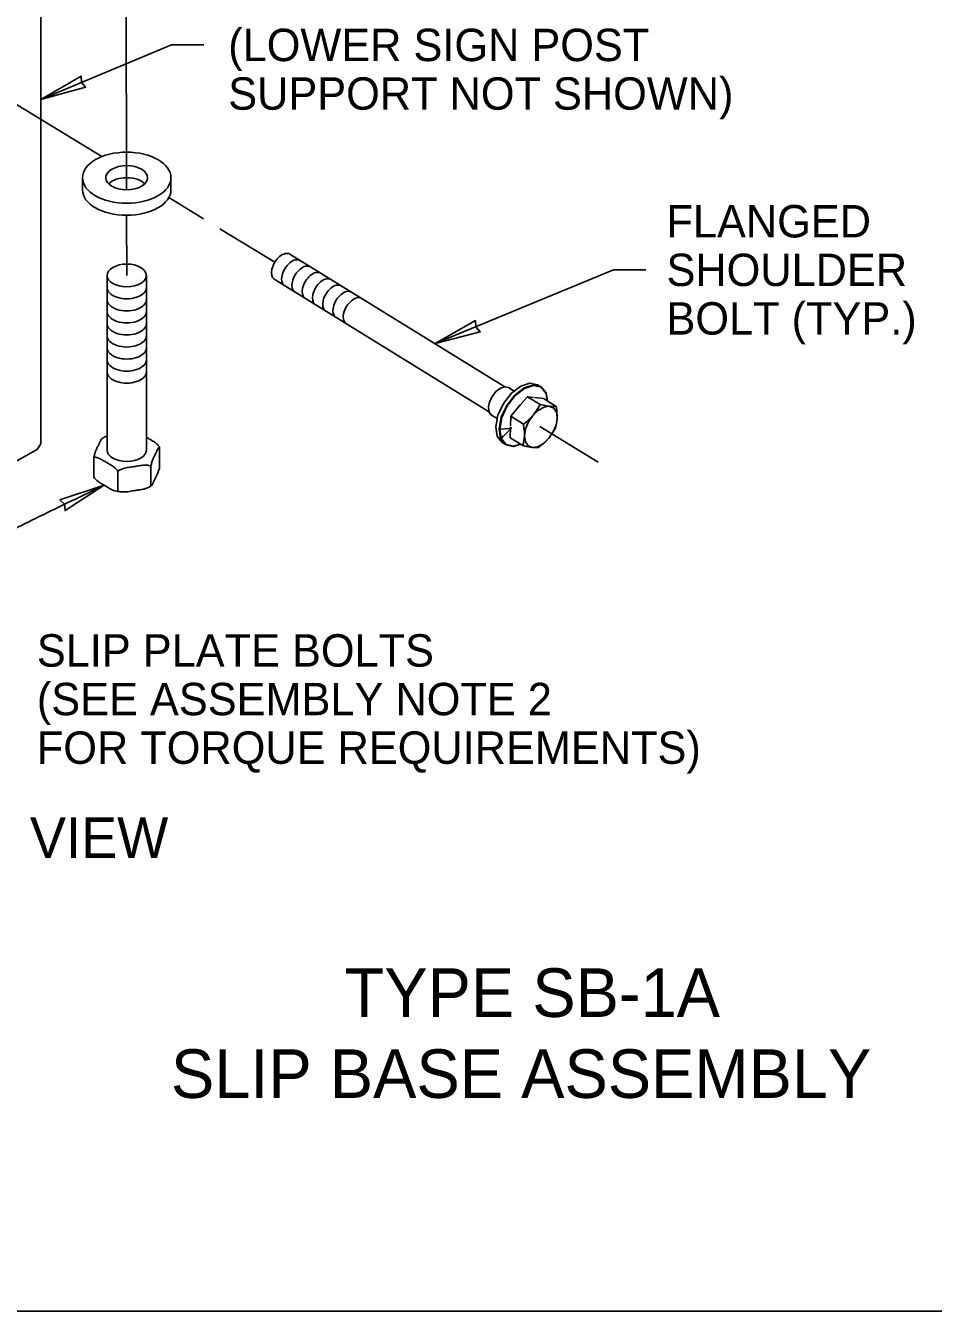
# Model space of a CAD drawing. Extents: x 99862 to 103151, y 99997 to 117076.
# Drawn here: x 100348 to 100796, y 112000 to 112634 of the extents above; entities that cross this region are included whole.
import ezdxf

# ---------------------------------------------------------------- set-up
doc = ezdxf.new("R2010")
doc.units = 0
for name, color, linetype in [('Level 1', 7, 'Continuous'), ('Level 12', 7, 'Continuous'), ('Level 13', 7, 'Continuous'), ('Level 15', 7, 'Continuous'), ('Level 20', 7, 'Continuous'), ('Level 3', 7, 'Continuous'), ('Level 4', 7, 'Continuous'), ('Level 5', 7, 'Continuous'), ('Level 9', 7, 'Continuous')]:
    doc.layers.add(name, color=color, linetype=linetype)

msp = doc.modelspace()

# ---------------------------------------------------------------- linework, layer by layer
at = {"layer": 'Level 1'}
msp.add_lwpolyline([(99862, 111999.5), (103151, 111999.5), (103151, 114075.5), (99862, 114075.5)], close=True, dxfattribs=at)
at = {"layer": 'Level 12'}
for p, q in [((100375.72, 112559.31), (100375.72, 112553.37)), ((100419.42, 112559.31), (100419.42, 112553.37)), ((100387.86, 112424.8), (100387.86, 112511.05)), ((100407.28, 112424.8), (100407.28, 112511.05)), ((100413.82, 112416.42), (100413.82, 112426.33)), ((100381.32, 112421.3), (100381.32, 112411.39)), ((100393.22, 112414.43), (100393.22, 112404.52)), ((100409.46, 112416.95), (100409.46, 112407.03))]:
    msp.add_line(p, q, dxfattribs=at)
for centre, major_axis in [((100397.57, 112559.31), (-21.85, 0)), ((100397.57, 112559.31), (-10.32, 0)), ((100397.57, 112511.05), (-9.71, 0))]:
    msp.add_ellipse(centre, major_axis=major_axis, ratio=0.57735, dxfattribs=at)
for centre, major_axis, start_param, end_param in [((100397.57, 112553.37), (-10.32, 0), 3.664192, 5.760586), ((100397.57, 112553.37), (21.85, 0), 3.141593, 6.283185), ((100397.57, 112505.1), (9.71, 0), 3.141588, 6.283185), ((100397.57, 112499.15), (9.71, 0), 3.141588, 6.283185), ((100397.57, 112493.2), (9.71, 0), 3.141588, 6.283185), ((100397.57, 112487.26), (9.71, 0), 3.141588, 6.283185), ((100397.57, 112481.31), (9.71, 0), 3.141588, 6.283185), ((100397.57, 112475.36), (9.71, 0), 3.141588, 6.283185), ((100397.57, 112469.41), (9.71, 0), 3.141588, 6.283185), ((100397.57, 112463.47), (9.71, 0), 3.141588, 6.283185), ((100397.57, 112424.8), (9.71, 0), 3.141593, 6.283185)]:
    msp.add_ellipse(centre, major_axis=major_axis, ratio=0.57735, start_param=start_param, end_param=end_param, dxfattribs=at)
for points, degree in [([(100387.86, 112431.72), (100387.5, 112431.6), (100387.15, 112431.47), (100386.64, 112431.24), (100386.46, 112431.15), (100386.28, 112431.05)], 3), ([(100385.55, 112430.63), (100385.49, 112430.6), (100385.43, 112430.54), (100384.81, 112429.88), (100384.09, 112428.26), (100383.5, 112426.98), (100382.9, 112425.69), (100382.19, 112424.24), (100381.53, 112422.09), (100381.42, 112421.7), (100381.32, 112421.3)], 3), ([(100386.28, 112431.05), (100386.06, 112430.93), (100385.84, 112430.81), (100385.61, 112430.67), (100385.58, 112430.65), (100385.55, 112430.63)], 3), ([(100413.82, 112426.33), (100413.56, 112426.67), (100413.25, 112427), (100411.44, 112428.77), (100409.5, 112429.81), (100407.87, 112430.75), (100407.68, 112430.86), (100407.48, 112430.97), (100407.28, 112431.09)], 3), ([(100413.82, 112426.33), (100413.72, 112426.32), (100413.61, 112426.23), (100412.95, 112425.53), (100412.24, 112423.9), (100411.64, 112422.62), (100411.05, 112421.34), (100410.33, 112419.89), (100409.67, 112417.74), (100409.56, 112417.34), (100409.46, 112416.95)], 3), ([(100393.22, 112414.43), (100392.96, 112414.78), (100392.65, 112415.11), (100390.84, 112416.87), (100388.89, 112417.91), (100387.27, 112418.85), (100385.64, 112419.79), (100383.69, 112421), (100381.88, 112421.32), (100381.58, 112421.35), (100381.32, 112421.3)], 3), ([(100409.46, 112416.95), (100409.11, 112417.09), (100408.69, 112417.18), (100406.22, 112417.52), (100403.56, 112417.02), (100401.34, 112416.68), (100399.12, 112416.33), (100396.46, 112416), (100393.99, 112414.9), (100393.57, 112414.68), (100393.22, 112414.43)], 3), ([(100409.59, 112407.08), (100409.65, 112407.12), (100409.71, 112407.17), (100410.33, 112407.84), (100411.05, 112409.46), (100411.64, 112410.74), (100412.24, 112412.02), (100412.95, 112413.47), (100413.61, 112415.62), (100413.72, 112416.02), (100413.82, 112416.42)], 3), ([(100381.32, 112411.39), (100381.58, 112411.04), (100381.88, 112410.71), (100383.69, 112408.95), (100385.64, 112407.91), (100387.27, 112406.97), (100388.87, 112406.04), (100390.78, 112404.86), (100392.31, 112404.56)], 3), ([(100394.56, 112404.21), (100396.62, 112403.98), (100399.19, 112404.46), (100401.34, 112404.79), (100403.56, 112405.13), (100406.22, 112405.46), (100408.5, 112406.48), (100408.68, 112406.57), (100408.87, 112406.67)], 3), ([(100408.86, 112406.66), (100409.08, 112406.78), (100409.3, 112406.9), (100409.53, 112407.04), (100409.56, 112407.06), (100409.59, 112407.08)], 3), ([(100392.31, 112404.56), (100393.06, 112404.41), (100393.81, 112404.3), (100394.56, 112404.21)], 2)]:
    msp.add_open_spline(points, degree=degree, dxfattribs=at)
at = {"layer": 'Level 13'}
for p, q in [((100584.37, 112456.08), (100478.11, 112521.57)), ((100576.32, 112443.93), (100470.47, 112509.17))]:
    msp.add_line(p, q, dxfattribs=at)
for centre, start_param, end_param in [((100474.29, 112515.37), 6.283173, 9.424785), ((100479.35, 112512.25), 6.283174, 9.424783), ((100484.42, 112509.13), 6.283172, 9.424785), ((100489.48, 112506.01), 6.283179, 9.424784), ((100494.55, 112502.88), 6.283177, 9.424782), ((100499.62, 112499.76), 6.283174, 9.424785), ((100504.68, 112496.64), 6.283176, 9.424783), ((100509.75, 112493.52), 6.283178, 9.42478)]:
    msp.add_ellipse(centre, major_axis=(3.82, 6.2), ratio=0.57735, start_param=start_param, end_param=end_param, dxfattribs=at)
at = {"layer": 'Level 15'}
for p, q in [((100397.47, 112553.36), (100397.16, 112677.54)), ((100355.06, 112597.97), (100419.74, 112624.88)), ((100435.74, 112624.88), (100419.74, 112624.88)), ((100385.2, 112569.71), (100315.22, 112612.39)), ((100435.56, 112539.01), (100418.37, 112549.49)), ((100397.57, 112511.05), (100397.5, 112540.75)), ((100470.71, 112517.58), (100443.53, 112534.15)), ((100549.96, 112477.36), (100638.07, 112513.82)), ((100654.07, 112513.82), (100638.07, 112513.82)), ((100630.48, 112418.83), (100601.66, 112436.41))]:
    msp.add_line(p, q, dxfattribs=at)
for points in [[(100355.06, 112597.97), (100377.28, 112603.99), (100375.16, 112606.34), (100374.99, 112609.5)], [(100549.96, 112477.36), (100572.21, 112483.25), (100570.11, 112485.61), (100569.95, 112488.77)], [(100386.47, 112407.43), (100367.14, 112394.91), (100366.81, 112398.06), (100364.57, 112400.3)]]:
    msp.add_lwpolyline(points, close=True, dxfattribs=at)
msp.add_open_spline([(100325.17, 112301.86), (100160.65, 112301.86), (100386.47, 112407.43)], degree=2, dxfattribs=at)
at = {"layer": 'Level 3'}
for p, q in [((100598.56, 112456.57), (100598.58, 112456.63)), ((100589.56, 112451.64), (100589.54, 112451.68)), ((100594.09, 112455.13), (100594.09, 112455.18)), ((100602.3, 112455.74), (100602.34, 112455.8)), ((100604.78, 112452.82), (100602.34, 112455.8)), ((100604.82, 112453.08), (100605.48, 112448.99)), ((100585.65, 112446.63), (100585.62, 112446.65)), ((100602.22, 112447.22), (100602.11, 112447.18)), ((100582.98, 112440.87), (100582.94, 112440.87)), ((100581.57, 112435.19), (100582.34, 112430.44)), ((100581.94, 112435.23), (100581.89, 112435.21)), ((100587.13, 112435.09), (100582.65, 112430.53)), ((100582.63, 112430.66), (100582.34, 112430.44)), ((100584.82, 112427.41), (100582.34, 112430.44)), ((100585.12, 112427.61), (100585.09, 112427.55)), ((100588.86, 112426.78), (100588.84, 112426.72))]:
    msp.add_line(p, q, dxfattribs=at)
for points in [[(100593.96, 112455.48), (100598.53, 112456.95), (100598.53, 112456.95)], [(100598.57, 112456.57), (100598.58, 112456.63), (100594.09, 112455.18)], [(100598.53, 112456.95), (100602.34, 112456.11), (100602.34, 112456.11)], [(100602.31, 112455.74), (100602.34, 112455.8), (100598.58, 112456.63)], [(100585.36, 112446.81), (100589.34, 112451.92), (100589.34, 112451.92)], [(100589.56, 112451.65), (100589.54, 112451.68), (100585.62, 112446.65)], [(100589.34, 112451.92), (100593.96, 112455.48), (100593.96, 112455.48)], [(100594.1, 112455.13), (100594.09, 112455.18), (100589.54, 112451.68)], [(100602.34, 112456.11), (100604.82, 112453.08), (100604.82, 112453.08)], [(100604.73, 112452.77), (100604.78, 112452.82), (100605.39, 112449.05)], [(100582.63, 112440.94), (100585.36, 112446.81), (100585.36, 112446.81)], [(100585.66, 112446.64), (100585.62, 112446.65), (100582.94, 112440.87)], [(100581.57, 112435.19), (100581.57, 112435.19), (100582.63, 112440.94), (100582.63, 112440.94)], [(100582.99, 112440.88), (100582.94, 112440.87), (100581.89, 112435.21)], [(100581.57, 112435.19), (100586.91, 112435.42), (100587.84, 112435.81)], [(100581.61, 112435.19), (100581.6, 112435.19), (100581.6, 112435.19), (100581.57, 112435.19)], [(100581.94, 112435.25), (100581.89, 112435.21), (100582.65, 112430.53)], [(100583.67, 112431.85), (100582.65, 112430.53), (100585.09, 112427.55)], [(100588.63, 112426.57), (100584.82, 112427.41), (100584.82, 112427.41)], [(100585.12, 112427.61), (100585.09, 112427.55), (100588.84, 112426.72)], [(100592.16, 112427.7), (100588.63, 112426.57), (100588.63, 112426.57)], [(100588.85, 112426.78), (100588.84, 112426.72), (100592.07, 112427.76)]]:
    msp.add_lwpolyline(points, dxfattribs=at)
at = {"layer": 'Level 4'}
for points in [[(100355.06, 112427.85), (100355.06, 112671.03)], [(100212.71, 112545.82), (100212.71, 112428.94), (100213.27, 112427.31), (100279.99, 112387), (100282.77, 112386.45), (100285, 112387), (100353.39, 112425.13), (100355.06, 112427.85)]]:
    msp.add_lwpolyline(points, dxfattribs=at)
at = {"layer": 'Level 5'}
for p, q in [((100601.95, 112456.19), (100600.6, 112457.02)), ((100582.42, 112430.47), (100582.4, 112430.48))]:
    msp.add_line(p, q, dxfattribs=at)
for points in [[(100584.56, 112427.72), (100583.12, 112428.61), (100580.65, 112431.62), (100579.88, 112436.34), (100580.94, 112442.04), (100583.66, 112447.86), (100587.63, 112452.91), (100592.24, 112456.43), (100596.8, 112457.87), (100600.6, 112457.02)], [(100580.62, 112440.35), (100577.82, 112442.08), (100576.64, 112443.52), (100576.27, 112445.78), (100576.31, 112446.33), (100576.78, 112448.51), (100578.08, 112451.29), (100579.98, 112453.71), (100582.19, 112455.39), (100584.37, 112456.08), (100586.19, 112455.68), (100588.99, 112453.95)], [(100582.31, 112430.59), (100582.31, 112430.6), (100581.54, 112435.31), (100582.6, 112441.02), (100585.32, 112446.84), (100589.29, 112451.89), (100589.84, 112452.3)], [(100592.17, 112427.7), (100592.15, 112427.68), (100591.86, 112427.61)]]:
    msp.add_lwpolyline(points, dxfattribs=at)
at = {"layer": 'Level 9'}
msp.add_line((100601.8, 112447.3), (100595.54, 112451.16), dxfattribs=at)
msp.add_line((100601.8, 112447.3), (100595.54, 112451.16), dxfattribs=at)
for points in [[(100598.61, 112450.79), (100595.54, 112451.16), (100592.5, 112447.59)], [(100598.61, 112450.79), (100595.54, 112451.16), (100592.5, 112447.59)], [(100610.3, 112440.89), (100610.3, 112441.01), (100610.05, 112444.29), (100610.02, 112444.72), (100609.74, 112446.37), (100603.48, 112450.22), (100599.02, 112450.75)], [(100610.3, 112440.89), (100610.3, 112441.01), (100610.05, 112444.29), (100610.02, 112444.72), (100609.74, 112446.37), (100603.48, 112450.22), (100599.02, 112450.75)], [(100592.36, 112447.41), (100587.31, 112441.48), (100587.17, 112436.59)], [(100592.36, 112447.41), (100587.31, 112441.48), (100587.17, 112436.59)], [(100599.76, 112443.82), (100598.48, 112442.15), (100601.04, 112444.55), (100603.78, 112446.05), (100606.3, 112446.43), (100605.41, 112446.56), (100603.43, 112446.97), (100601.8, 112447.3), (100600.65, 112445.35), (100599.76, 112443.82)], [(100599.76, 112443.82), (100598.48, 112442.15), (100601.04, 112444.55), (100603.78, 112446.05), (100606.3, 112446.43), (100605.41, 112446.56), (100603.43, 112446.97), (100601.8, 112447.3), (100600.65, 112445.35), (100599.76, 112443.82)], [(100606.3, 112446.43), (100606.64, 112446.39), (100607.09, 112446.34), (100608.7, 112446.32), (100609.09, 112446.31), (100609.74, 112446.37)], [(100606.3, 112446.43), (100606.64, 112446.39), (100607.09, 112446.34), (100608.7, 112446.32), (100609.09, 112446.31), (100609.74, 112446.37)], [(100606.64, 112446.39), (100608.59, 112445.5), (100609.87, 112443.57), (100610.3, 112440.89)], [(100606.64, 112446.39), (100608.59, 112445.5), (100609.87, 112443.57), (100610.3, 112440.89)], [(100587.31, 112441.48), (100593.57, 112437.63), (100595.02, 112438.76), (100595.42, 112439.14), (100598.1, 112441.7), (100598.29, 112441.93), (100598.48, 112442.15)], [(100587.31, 112441.48), (100593.57, 112437.63), (100595.02, 112438.76), (100595.42, 112439.14), (100598.1, 112441.7), (100598.29, 112441.93), (100598.48, 112442.15)], [(100593.57, 112437.63), (100593.86, 112435.46), (100594.07, 112433.9), (100594.1, 112431.84), (100594.11, 112431.53), (100593.68, 112428.64), (100593.63, 112428.28), (100593.27, 112427.02)], [(100593.57, 112437.63), (100593.86, 112435.46), (100594.07, 112433.9), (100594.1, 112431.84), (100594.11, 112431.53), (100593.68, 112428.64), (100593.63, 112428.28), (100593.27, 112427.02)], [(100597.94, 112426.12), (100595.9, 112426.97), (100594.54, 112428.95), (100594.12, 112431.83), (100594.68, 112435.25), (100596.16, 112438.8), (100598.29, 112441.93)], [(100597.94, 112426.12), (100595.9, 112426.97), (100594.54, 112428.95), (100594.12, 112431.83), (100594.68, 112435.25), (100596.16, 112438.8), (100598.29, 112441.93)], [(100610.28, 112440.39), (100609.69, 112437.14), (100608.25, 112433.74), (100606.18, 112430.67)], [(100610.28, 112440.39), (100609.69, 112437.14), (100608.25, 112433.74), (100606.18, 112430.67)], [(100610.3, 112440.89), (100610.28, 112440.39), (100610.15, 112438.81), (100609.81, 112437.37), (100609.44, 112435.76)], [(100610.3, 112440.89), (100610.28, 112440.39), (100610.15, 112438.81), (100609.81, 112437.37), (100609.44, 112435.76)], [(100587.16, 112436.2), (100587.01, 112430.87), (100593.27, 112427.02), (100595.09, 112426.64), (100596.87, 112426.27), (100597.94, 112426.12)], [(100587.16, 112436.2), (100587.01, 112430.87), (100593.27, 112427.02), (100595.09, 112426.64), (100596.87, 112426.27), (100597.94, 112426.12)], [(100605.88, 112430.32), (100606.18, 112430.67), (100606.31, 112430.83), (100608.34, 112433.8), (100608.63, 112434.24), (100609.44, 112435.76)], [(100605.88, 112430.32), (100606.18, 112430.67), (100606.31, 112430.83), (100608.34, 112433.8), (100608.63, 112434.24), (100609.44, 112435.76)], [(100605.88, 112430.32), (100604.47, 112428.83), (100602.91, 112427.51), (100601.21, 112426.09), (100600.56, 112426.02), (100600.1, 112426.01), (100600.07, 112426), (100597.94, 112426.12)], [(100597.94, 112426.12), (100600.48, 112426.43), (100603.26, 112427.91), (100605.88, 112430.32)], [(100605.88, 112430.32), (100604.47, 112428.83), (100602.91, 112427.51), (100601.21, 112426.09), (100600.56, 112426.02), (100600.1, 112426.01), (100600.07, 112426), (100597.94, 112426.12)], [(100597.94, 112426.12), (100600.48, 112426.43), (100603.26, 112427.91), (100605.88, 112430.32)]]:
    msp.add_lwpolyline(points, dxfattribs=at)

# ---------------------------------------------------------------- texts
at = {"layer": 'Level 20'}
for s, height, p in [('(LOWER SIGN POST', 16, (100447.73, 112616.89)), ('SUPPORT NOT SHOWN)', 16, (100447.73, 112592.89)), ('FLANGED ', 16, (100664.26, 112529.82)), ('SHOULDER ', 16, (100664.26, 112505.82)), ('BOLT (TYP.)', 16, (100664.26, 112481.82)), ('SLIP PLATE BOLTS ', 16, (100353.17, 112317.86)), ('(SEE ASSEMBLY NOTE 2  ', 16, (100353.17, 112293.86)), ('FOR TORQUE REQUIREMENTS)', 16, (100353.17, 112269.86)), ('EXPLODED VIEW', 20, (100196.66, 112223.41)), ('TYPE SB-1A', 24, (100505.22, 112144.86)), ('SLIP BASE ASSEMBLY', 24, (100419.41, 112104.86))]:
    msp.add_text(s, height=height, dxfattribs=at).set_placement(p)

doc.saveas('drawing.dxf')
